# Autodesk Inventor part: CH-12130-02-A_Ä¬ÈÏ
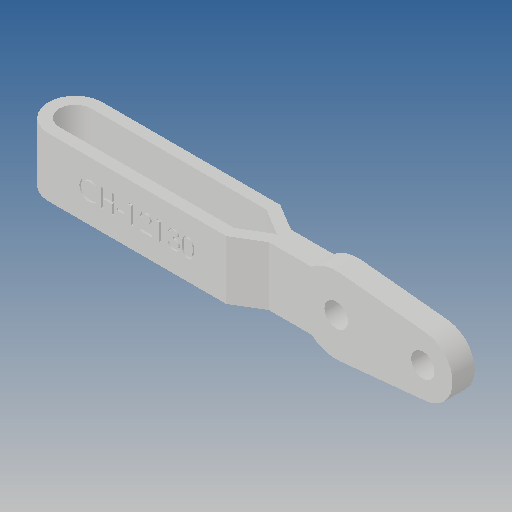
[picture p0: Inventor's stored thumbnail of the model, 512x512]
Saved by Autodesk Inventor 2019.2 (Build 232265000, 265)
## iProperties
Created: 2010-06
Part Number: CH-12130-02-A_Ä¬ÈÏ
Material: Ogólny
Document SubType Name: Modeling
Designer: CADENGINEERING4
Density: 1 g/cm^3
Appearance: Domyślna
Author: CADENGINEERING4
Revision Number: ÈÎºÎ
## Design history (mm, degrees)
feature "NONE"
node "Bryła1"
